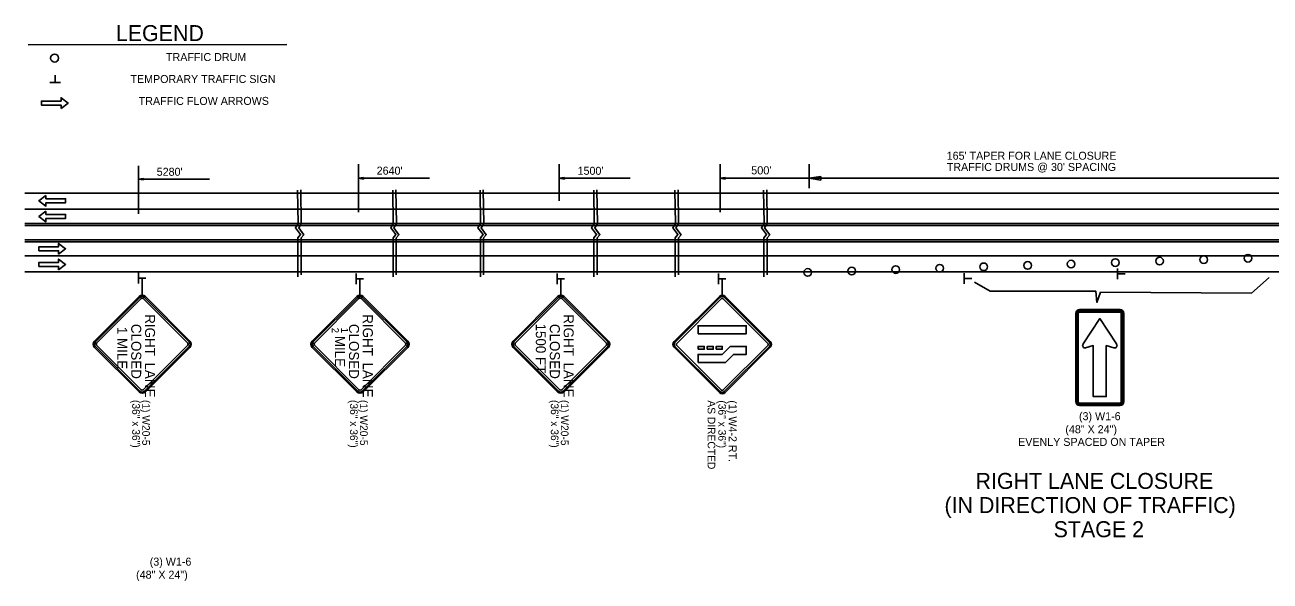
# Model space of a CAD drawing. Extents: x 1930579 to 1937984, y 596452 to 597630.
# Drawn here: x 1936493 to 1937427, y 597199 to 597617 of the extents above; entities that cross this region are included whole.
import ezdxf

# ---------------------------------------------------------------- set-up
doc = ezdxf.new("R2010")
doc.units = 0
for name, color, linetype in [('Default', 7, 'Continuous'), ('P_TC_Signs_Permanent', 7, 'Continuous'), ('P_TC_Signs_Temporary', 7, 'Continuous'), ('R_Annotation', 7, 'Continuous'), ('R_MOT', 7, 'Continuous'), ('R_Striping', 7, 'Continuous')]:
    doc.layers.add(name, color=color, linetype=linetype)

msp = doc.modelspace()

# ---------------------------------------------------------------- linework, layer by layer
at = {"layer": 'Default'}
for p, q in [((1936578.22, 597510.73), (1936578.22, 597474.82)), ((1936743.12, 597511.96), (1936743.12, 597476.04)), ((1936893.76, 597511.96), (1936893.76, 597484.57)), ((1937014.32, 597511.96), (1937014.32, 597476.04)), ((1937081.1, 597511.96), (1937081.1, 597493.95)), ((1936582.04, 597501.32), (1936578.22, 597500.75)), ((1936578.22, 597500.75), (1936631.45, 597500.75)), ((1936582.04, 597500.17), (1936578.22, 597500.75)), ((1936582.04, 597501.23), (1936578.85, 597500.75)), ((1936582.04, 597500.27), (1936578.85, 597500.75)), ((1936582.04, 597501.13), (1936579.51, 597500.75)), ((1936582.04, 597500.37), (1936579.51, 597500.75)), ((1936582.04, 597501.03), (1936580.15, 597500.75)), ((1936582.04, 597500.46), (1936580.15, 597500.75)), ((1936582.04, 597500.94), (1936580.8, 597500.75)), ((1936582.04, 597500.56), (1936580.8, 597500.75)), ((1936582.04, 597500.84), (1936581.44, 597500.75)), ((1936582.04, 597500.66), (1936581.44, 597500.75)), ((1936582.04, 597500.17), (1936582.04, 597501.32)), ((1936746.94, 597502), (1936743.12, 597501.43)), ((1936743.12, 597501.43), (1936796.35, 597501.43)), ((1936746.94, 597500.85), (1936743.12, 597501.43)), ((1936746.94, 597501.91), (1936743.76, 597501.43)), ((1936746.94, 597500.95), (1936743.76, 597501.43)), ((1936746.94, 597501.81), (1936744.42, 597501.43)), ((1936746.94, 597501.05), (1936744.42, 597501.43)), ((1936746.94, 597501.71), (1936745.05, 597501.43)), ((1936746.94, 597501.14), (1936745.05, 597501.43)), ((1936746.94, 597501.62), (1936745.7, 597501.43)), ((1936746.94, 597501.24), (1936745.7, 597501.43)), ((1936746.94, 597501.52), (1936746.34, 597501.43)), ((1936746.94, 597501.34), (1936746.34, 597501.43)), ((1936746.94, 597500.85), (1936746.94, 597502)), ((1936897.58, 597502), (1936893.76, 597501.43)), ((1936893.76, 597501.43), (1936946.99, 597501.43)), ((1936897.58, 597500.85), (1936893.76, 597501.43)), ((1936897.58, 597501.91), (1936894.4, 597501.43)), ((1936897.58, 597500.95), (1936894.4, 597501.43)), ((1936897.58, 597501.81), (1936895.05, 597501.43)), ((1936897.58, 597501.05), (1936895.05, 597501.43)), ((1936897.58, 597501.71), (1936895.69, 597501.43)), ((1936897.58, 597501.14), (1936895.69, 597501.43)), ((1936897.58, 597501.62), (1936896.34, 597501.43)), ((1936897.58, 597501.24), (1936896.34, 597501.43)), ((1936897.58, 597501.52), (1936896.98, 597501.43)), ((1936897.58, 597501.34), (1936896.98, 597501.43)), ((1936897.58, 597500.85), (1936897.58, 597502)), ((1937018.15, 597502), (1937014.32, 597501.43)), ((1937014.32, 597501.43), (1937081.1, 597501.43)), ((1937018.15, 597500.85), (1937014.32, 597501.43)), ((1937018.15, 597501.91), (1937014.96, 597501.43)), ((1937018.15, 597500.95), (1937014.96, 597501.43)), ((1937018.15, 597501.81), (1937015.62, 597501.43)), ((1937018.15, 597501.05), (1937015.62, 597501.43)), ((1937018.15, 597501.71), (1937016.26, 597501.43)), ((1937018.15, 597501.14), (1937016.26, 597501.43)), ((1937018.15, 597501.62), (1937016.9, 597501.43)), ((1937018.15, 597501.24), (1937016.9, 597501.43)), ((1937018.15, 597501.52), (1937017.54, 597501.43)), ((1937018.15, 597501.34), (1937017.54, 597501.43)), ((1937018.15, 597500.85), (1937018.15, 597502)), ((1937081.1, 597501.43), (1937089.97, 597502.76)), ((1937448.32, 597501.43), (1937081.1, 597501.43)), ((1937089.97, 597500.1), (1937081.1, 597501.43)), ((1937089.97, 597502.76), (1937089.97, 597500.1)), ((1936671.76, 597490.19), (1936493.11, 597490.19)), ((1937700.06, 597490.19), (1936671.76, 597490.19)), ((1937700.06, 597478.19), (1936493.11, 597478.19)), ((1936671.76, 597467.4), (1936493.11, 597467.4)), ((1936671.76, 597466.02), (1936493.11, 597466.02)), ((1937700.06, 597467.4), (1936671.76, 597467.4)), ((1937700.06, 597466.02), (1936671.76, 597466.02)), ((1936671.76, 597455.23), (1936493.11, 597455.23)), ((1936671.76, 597453.85), (1936493.11, 597453.85)), ((1937700.06, 597455.23), (1936671.76, 597455.23)), ((1937700.06, 597453.85), (1936671.76, 597453.85)), ((1937700.06, 597443.19), (1936493.11, 597443.19)), ((1937312.37, 597425.75), (1937312.37, 597433.73)), ((1936671.76, 597431.19), (1936493.11, 597431.19)), ((1936578.22, 597422.6), (1936578.22, 597430.58)), ((1936578.33, 597426.56), (1936583.78, 597426.56)), ((1936666.15, 597431.19), (1936671.76, 597431.19)), ((1937700.06, 597431.19), (1936671.76, 597431.19)), ((1936741.5, 597422.09), (1936741.5, 597430.07)), ((1936741.62, 597426.06), (1936747.07, 597426.06)), ((1936892.08, 597422.09), (1936892.08, 597430.07)), ((1936892.2, 597426.06), (1936897.64, 597426.06)), ((1937013.04, 597422.09), (1937013.04, 597430.07)), ((1937013.16, 597426.05), (1937018.6, 597426.05)), ((1937197.41, 597422.26), (1937197.41, 597430.24)), ((1937197.52, 597426.23), (1937202.97, 597426.23)), ((1937312.49, 597429.72), (1937317.93, 597429.72))]:
    msp.add_line(p, q, dxfattribs=at)
for points in [[(1936697.54, 597492.48), (1936697.92, 597467.24), (1936695.97, 597464.34), (1936699.77, 597459.14), (1936697.77, 597456.74), (1936697.77, 597427.4)], [(1936699.93, 597492.71), (1936700.32, 597467.14), (1936698.37, 597464.24), (1936702.17, 597459.04), (1936700.17, 597456.64), (1936700.17, 597429.08)], [(1936768.9, 597492.48), (1936769.29, 597467.24), (1936767.34, 597464.34), (1936771.13, 597459.14), (1936769.14, 597456.74), (1936769.13, 597427.4)], [(1936771.3, 597492.71), (1936771.68, 597467.14), (1936769.74, 597464.24), (1936773.53, 597459.04), (1936771.53, 597456.64), (1936771.53, 597429.08)], [(1936834.34, 597492.48), (1936834.73, 597467.24), (1936832.78, 597464.34), (1936836.58, 597459.14), (1936834.58, 597456.74), (1936834.57, 597427.4)], [(1936836.74, 597492.71), (1936837.13, 597467.14), (1936835.18, 597464.24), (1936838.97, 597459.04), (1936836.98, 597456.64), (1936836.97, 597429.08)], [(1936919.54, 597492.48), (1936919.92, 597467.24), (1936917.97, 597464.34), (1936921.77, 597459.14), (1936919.77, 597456.74), (1936919.77, 597427.4)], [(1936921.93, 597492.71), (1936922.32, 597467.14), (1936920.37, 597464.24), (1936924.17, 597459.04), (1936922.17, 597456.64), (1936922.17, 597429.08)], [(1936980.42, 597492.48), (1936980.81, 597467.24), (1936978.86, 597464.34), (1936982.66, 597459.14), (1936980.66, 597456.74), (1936980.65, 597427.4)], [(1936982.82, 597492.71), (1936983.2, 597467.14), (1936981.26, 597464.24), (1936985.05, 597459.04), (1936983.05, 597456.64), (1936983.05, 597429.08)], [(1937046.88, 597492.48), (1937047.26, 597467.24), (1937045.32, 597464.34), (1937049.11, 597459.14), (1937047.11, 597456.74), (1937047.11, 597427.4)], [(1937049.27, 597492.71), (1937049.66, 597467.14), (1937047.71, 597464.24), (1937051.51, 597459.04), (1937049.51, 597456.64), (1937049.51, 597429.08)]]:
    msp.add_lwpolyline(points, dxfattribs=at)
for centre, radius in [((1936515.36, 597591.57), 3), ((1937376.94, 597440.38), 2.87), ((1937410.09, 597441.48), 2.87), ((1937080.03, 597430.82), 2.87), ((1937113.01, 597431.86), 2.87), ((1937145.99, 597432.91), 2.87), ((1937178.98, 597433.95), 2.87), ((1937211.96, 597435), 2.87), ((1937244.94, 597436.04), 2.87), ((1937277.48, 597437.08), 2.87), ((1937310.63, 597438.18), 2.87), ((1937343.78, 597439.28), 2.87)]:
    msp.add_circle(centre, radius, dxfattribs=at)
at = {"layer": 'P_TC_Signs_Permanent'}
for p, q in [((1936979.82, 597378.89), (1937013.76, 597412.83)), ((1937281.01, 597400.12), (1937281.01, 597333.75)), ((1937281.76, 597400.12), (1937281.76, 597333.75)), ((1937282.89, 597400.12), (1937282.89, 597333.75)), ((1937314.2, 597402.94), (1937283.83, 597402.94)), ((1937314.2, 597402.19), (1937283.83, 597402.19)), ((1937314.2, 597401.06), (1937283.83, 597401.06)), ((1937315.14, 597333.75), (1937315.14, 597400.12)), ((1937316.26, 597333.75), (1937316.26, 597400.12)), ((1937317.01, 597333.75), (1937317.01, 597400.12)), ((1937033.88, 597384.81), (1937033.88, 597390.81)), ((1937013.76, 597340.7), (1936979.82, 597374.65)), ((1937051.94, 597374.65), (1937018, 597340.7)), ((1937283.83, 597332.81), (1937314.2, 597332.81)), ((1937283.83, 597331.69), (1937314.2, 597331.69)), ((1937283.83, 597330.94), (1937314.2, 597330.94))]:
    msp.add_line(p, q, dxfattribs=at)
for points in [[(1937014.4, 597412.19), (1936980.46, 597378.25)], [(1936981.52, 597377.19), (1937015.46, 597411.13)], [(1937016.31, 597411.13), (1937050.25, 597377.19)], [(1937051.31, 597378.25), (1937017.37, 597412.19)], [(1937018, 597412.83), (1937034.97, 597395.86), (1937051.94, 597378.89)], [(1937311.46, 597377.19), (1937299.01, 597396.19), (1937286.61, 597377.18)], [(1936980.46, 597375.28), (1937014.4, 597341.34)], [(1937015.46, 597342.4), (1936981.52, 597376.34)], [(1937050.25, 597376.34), (1937016.31, 597342.4)], [(1937017.37, 597341.34), (1937051.31, 597375.28)], [(1937288.38, 597374.23), (1937294.14, 597375.95), (1937294.14, 597337.69), (1937303.89, 597337.69), (1937303.89, 597375.95), (1937309.64, 597374.2)]]:
    msp.add_lwpolyline(points, dxfattribs=at)
for points in [[(1936997.88, 597384.81), (1936997.88, 597390.81), (1937033.88, 597390.81), (1937033.88, 597384.81)], [(1936997.88, 597373.17), (1936997.88, 597375.27), (1937002.38, 597375.27), (1937002.38, 597373.17)], [(1936997.88, 597363.27), (1936997.88, 597369.27), (1937015.88, 597369.27), (1937021.88, 597375.27), (1937033.88, 597375.27), (1937033.88, 597369.27), (1937024.37, 597369.27), (1937018.37, 597363.27)], [(1937004.63, 597373.17), (1937004.63, 597375.27), (1937009.13, 597375.27), (1937009.13, 597373.17)], [(1937011.38, 597373.17), (1937011.38, 597375.27), (1937015.88, 597375.27), (1937015.88, 597373.17)]]:
    msp.add_lwpolyline(points, close=True, dxfattribs=at)
for centre, radius, start, end in [((1937015.88, 597410.71), 3, 45, 135), ((1937015.88, 597410.71), 2.1, 45, 135), ((1937015.88, 597410.71), 0.6, 45, 135), ((1937283.83, 597400.12), 2.81, 90, 180), ((1937283.83, 597400.12), 2.06, 90, 180), ((1937283.83, 597400.12), 0.938, 90, 180), ((1937314.2, 597400.12), 2.81, 360, 90), ((1937314.2, 597400.12), 2.06, 360, 90), ((1937314.2, 597400.12), 0.938, 360, 90), ((1936981.94, 597376.77), 3, 135, 225), ((1936981.94, 597376.77), 2.1, 135, 225), ((1937049.82, 597376.77), 2.1, 315, 45), ((1937049.82, 597376.77), 3, 315, 45), ((1936981.94, 597376.77), 0.6, 135, 225), ((1937049.82, 597376.77), 0.6, 315, 45), ((1937287.9, 597375.93), 1.76, 146.59943, 285.96908), ((1937223.81, 597418.19), 75, 326.59943, 326.85697), ((1937310.13, 597375.93), 1.8, 254.03093, 33.47548), ((1937374.19, 597418.29), 75, 213.2286, 213.47548), ((1937015.88, 597342.83), 3, 225, 315), ((1937015.88, 597342.83), 2.1, 225, 315), ((1937015.88, 597342.83), 0.6, 225, 315), ((1937283.83, 597333.75), 2.81, 180, 270), ((1937283.83, 597333.75), 2.06, 180, 270), ((1937283.83, 597333.75), 0.937, 180, 270), ((1937314.2, 597333.75), 2.81, 270, 360), ((1937314.2, 597333.75), 2.06, 270, 360), ((1937314.2, 597333.75), 0.938, 270, 360)]:
    msp.add_arc(centre, radius, start, end, dxfattribs=at)
at = {"layer": 'P_TC_Signs_Temporary'}
for p, q in [((1936545.26, 597379.31), (1936578.67, 597412.72)), ((1936545.92, 597378.65), (1936579.33, 597412.06)), ((1936546.85, 597377.72), (1936580.26, 597411.13)), ((1936581.85, 597411.13), (1936615.26, 597377.72)), ((1936582.78, 597412.06), (1936616.19, 597378.65)), ((1936583.44, 597412.72), (1936616.85, 597379.31)), ((1936708.54, 597379.31), (1936741.96, 597412.72)), ((1936709.21, 597378.65), (1936742.62, 597412.06)), ((1936710.14, 597377.72), (1936743.55, 597411.13)), ((1936745.14, 597411.13), (1936778.55, 597377.72)), ((1936746.07, 597412.06), (1936779.48, 597378.65)), ((1936746.73, 597412.72), (1936780.14, 597379.31)), ((1936859.12, 597379.31), (1936892.53, 597412.72)), ((1936859.79, 597378.65), (1936893.2, 597412.06)), ((1936860.71, 597377.72), (1936894.12, 597411.13)), ((1936895.72, 597411.13), (1936929.13, 597377.72)), ((1936896.64, 597412.06), (1936930.05, 597378.65)), ((1936897.31, 597412.72), (1936930.72, 597379.31)), ((1936578.67, 597341.12), (1936545.26, 597374.54)), ((1936579.33, 597341.79), (1936545.92, 597375.2)), ((1936580.26, 597342.72), (1936546.85, 597376.13)), ((1936615.26, 597376.13), (1936581.85, 597342.72)), ((1936616.19, 597375.2), (1936582.78, 597341.79)), ((1936616.85, 597374.54), (1936583.44, 597341.12)), ((1936741.96, 597341.12), (1936708.54, 597374.54)), ((1936742.62, 597341.79), (1936709.21, 597375.2)), ((1936743.55, 597342.72), (1936710.14, 597376.13)), ((1936778.55, 597376.13), (1936745.14, 597342.72)), ((1936779.48, 597375.2), (1936746.07, 597341.79)), ((1936780.14, 597374.54), (1936746.73, 597341.12)), ((1936892.53, 597341.12), (1936859.12, 597374.54)), ((1936893.2, 597341.79), (1936859.79, 597375.2)), ((1936894.12, 597342.72), (1936860.71, 597376.13)), ((1936929.13, 597376.13), (1936895.72, 597342.72)), ((1936930.05, 597375.2), (1936896.64, 597341.79)), ((1936930.72, 597374.54), (1936897.31, 597341.12))]:
    msp.add_line(p, q, dxfattribs=at)
for centre, radius, start, end in [((1936581.06, 597410.33), 3.37, 45, 135), ((1936581.06, 597410.33), 2.44, 45, 135), ((1936581.06, 597410.33), 1.12, 45, 135), ((1936744.34, 597410.33), 3.37, 45, 135), ((1936744.34, 597410.33), 2.44, 45, 135), ((1936744.34, 597410.33), 1.12, 45, 135), ((1936894.92, 597410.33), 3.37, 45, 135), ((1936894.92, 597410.33), 2.44, 45, 135), ((1936894.92, 597410.33), 1.12, 45, 135), ((1936547.65, 597376.92), 3.37, 135, 225), ((1936547.65, 597376.92), 2.44, 135, 225), ((1936547.65, 597376.92), 1.13, 135, 225), ((1936614.47, 597376.92), 1.13, 315, 45), ((1936614.47, 597376.92), 2.44, 315, 45), ((1936614.47, 597376.92), 3.38, 315, 45), ((1936710.93, 597376.92), 3.37, 135, 225), ((1936710.93, 597376.92), 2.44, 135, 225), ((1936710.93, 597376.92), 1.13, 135, 225), ((1936777.75, 597376.92), 1.13, 315, 45), ((1936777.75, 597376.92), 2.44, 315, 45), ((1936777.75, 597376.92), 3.38, 315, 45), ((1936861.51, 597376.92), 3.37, 135, 225), ((1936861.51, 597376.92), 2.44, 135, 225), ((1936861.51, 597376.92), 1.13, 135, 225), ((1936928.33, 597376.92), 1.13, 315, 45), ((1936928.33, 597376.92), 2.44, 315, 45), ((1936928.33, 597376.92), 3.38, 315, 45), ((1936581.06, 597343.51), 3.38, 225, 315), ((1936581.06, 597343.51), 2.44, 225, 315), ((1936581.06, 597343.51), 1.12, 225, 315), ((1936744.34, 597343.51), 3.38, 225, 315), ((1936744.34, 597343.51), 2.44, 225, 315), ((1936744.34, 597343.51), 1.12, 225, 315), ((1936894.92, 597343.51), 3.38, 225, 315), ((1936894.92, 597343.51), 2.44, 225, 315), ((1936894.92, 597343.51), 1.12, 225, 315)]:
    msp.add_arc(centre, radius, start, end, dxfattribs=at)
at = {"layer": 'R_Annotation'}
for p, q in [((1936495.59, 597601.6), (1936689.5, 597601.73)), ((1936515.74, 597573.4), (1936515.74, 597578.86)), ((1936519.72, 597573.29), (1936511.72, 597573.28)), ((1936581.06, 597426.56), (1936581.06, 597413.64)), ((1936744.34, 597426.06), (1936744.34, 597413.71)), ((1936894.92, 597426.06), (1936894.92, 597413.71)), ((1937015.88, 597426.05), (1937015.88, 597413.71))]:
    msp.add_line(p, q, dxfattribs=at)
msp.add_lwpolyline([(1937205.08, 597423.61), (1937216.89, 597416.66), (1937296.1, 597416.66), (1937296.79, 597408.32), (1937299.57, 597415.97), (1937412.82, 597415.27), (1937426.02, 597427.09)], dxfattribs=at)
at = {"layer": 'R_MOT'}
msp.add_lwpolyline([(1936520.24, 597553.89), (1936525.43, 597557.89), (1936520.23, 597561.89), (1936520.23, 597559.39), (1936505.52, 597559.38), (1936505.52, 597556.38), (1936520.24, 597556.39)], close=True, dxfattribs=at)
at = {"layer": 'R_Striping'}
for points in [[(1936508.84, 597488.56), (1936503.65, 597484.56), (1936508.84, 597480.56), (1936508.84, 597483.06), (1936523.56, 597483.06), (1936523.56, 597486.06), (1936508.84, 597486.06)], [(1936508.84, 597476.78), (1936503.65, 597472.78), (1936508.84, 597468.78), (1936508.84, 597471.28), (1936523.56, 597471.28), (1936523.56, 597474.28), (1936508.84, 597474.28)], [(1936518.36, 597444.54), (1936523.56, 597448.54), (1936518.36, 597452.54), (1936518.36, 597450.04), (1936503.65, 597450.04), (1936503.65, 597447.04), (1936518.36, 597447.04)], [(1936518.36, 597432.76), (1936523.56, 597436.76), (1936518.36, 597440.76), (1936518.36, 597438.26), (1936503.65, 597438.26), (1936503.65, 597435.26), (1936518.36, 597435.26)]]:
    msp.add_lwpolyline(points, close=True, dxfattribs=at)

# ---------------------------------------------------------------- texts
at = {"layer": 'Default'}
for s, height, p in [("165' TAPER FOR LANE CLOSURE", 6, (1937184.21, 597515.36)), ("5280'", 6, (1936591.93, 597503.32)), ("2640'", 6, (1936756.84, 597504.15)), ("1500'", 6, (1936907.47, 597504.06)), ("500'", 6.12, (1937037.61, 597504.34)), ("TRAFFIC DRUMS @ 30' SPACING", 6, (1937184.28, 597506.93)), ('RIGHT LANE CLOSURE', 12, (1937205.79, 597268.37)), ('(IN DIRECTION OF TRAFFIC)', 12, (1937182.54, 597250.25)), ('STAGE 2', 12, (1937264.37, 597232.13))]:
    msp.add_text(s, height=height, rotation=360, dxfattribs=at).set_placement(p)
at = {"layer": 'P_TC_Signs_Temporary'}
for s, height, p in [('RIGHT\u2002LANE', 7.5, (1936583.18, 597399.44)), ('RIGHT\u2002LANE', 7.5, (1936746.47, 597399.44)), ('RIGHT\u2002LANE', 7.5, (1936897.05, 597399.44)), ('1 MILE', 7.5, (1936562.31, 597389.97)), ('CLOSED', 7.5, (1936572.81, 597392.17)), ('2', 5.25, (1936723.22, 597389.27)), ('1', 5.25, (1936730.22, 597389.27)), ('CLOSED', 7.5, (1936736.09, 597392.17)), ('1500 FT', 7.5, (1936876.17, 597392.44)), ('CLOSED', 7.5, (1936886.67, 597392.17)), (' MILE', 7.5, (1936725.59, 597386.01))]:
    msp.add_text(s, height=height, rotation=270, dxfattribs=at).set_placement(p)
at = {"layer": 'R_Annotation'}
for s, height, rotation, p in [('LEGEND', 12, 0.03878, (1936561.32, 597604.33)), ('TRAFFIC DRUM', 6, 0.03876, (1936598.9, 597589.37)), ('TEMPORARY TRAFFIC SIGN', 6, 0.03876, (1936572.23, 597572.89)), ('TRAFFIC FLOW ARROWS', 6, 0.03876, (1936578.44, 597556.43)), ('(36" x 36")', 5.76, 270, (1936573.57, 597335.15)), ('(1) W20-5', 5.76, 270, (1936581.06, 597335.15)), ('(36" x 36")', 5.76, 270, (1936736.85, 597335.14)), ('(1) W20-5', 5.76, 270, (1936744.34, 597335.14)), ('(36" x 36")', 5.76, 270, (1936887.43, 597335.14)), ('(1) W20-5', 5.76, 270, (1936894.92, 597335.14)), ('AS DIRECTED ', 5.76, 270, (1937004.99, 597334.83)), ('(36" x 36")', 5.76, 270, (1937013, 597334.83)), ('(1) W4-2 RT.', 6, 270, (1937020.77, 597334.83)), ('(3) W1-6', 6, 0.00754, (1937283.4, 597319.93)), ('(48" X 24")', 6, 0.00754, (1937273.17, 597310.13)), ('EVENLY SPACED ON TAPER', 6, 0.00754, (1937237.76, 597300.64)), ('(3) W1-6', 6, 0.00754, (1936586.71, 597210.8)), ('(48" X 24")', 6, 0.00754, (1936576.48, 597201))]:
    msp.add_text(s, height=height, rotation=rotation, dxfattribs=at).set_placement(p)

doc.saveas('drawing.dxf')
